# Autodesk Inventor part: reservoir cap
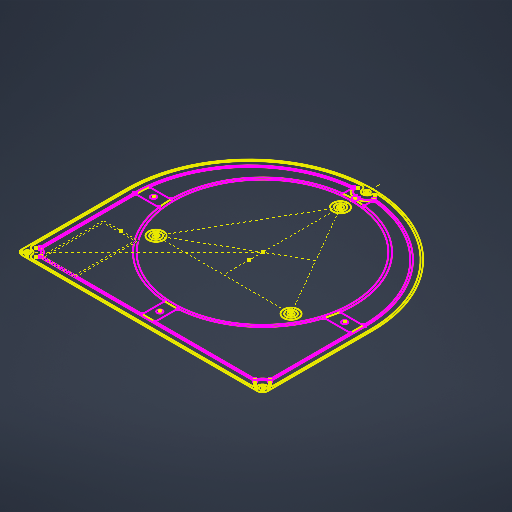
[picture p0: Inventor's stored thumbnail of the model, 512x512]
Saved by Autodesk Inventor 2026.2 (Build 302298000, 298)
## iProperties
Created: 2026-03
Part Number: reservoir cap
Material: Generic
Document SubType Name: Modeling
Designer: Tathagata Sikdar
Density: 1 g/cm^3
Appearance: Default
Author: Tathagata Sikdar
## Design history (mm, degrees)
derived "camera_base.ipt"
  sketch "Sketch1"
    geometry: L1 (0, -60.044)-(52, 30.022) reference; L2 (52, 30.022)-(-52, 30.022) reference; L3 (-52, 30.022)-(0, -60.044) reference; L4 (-26, -15.011)-(52, 30.022) reference; L5 (0, -60.044)-(0, 30.022) reference; L6 (94.574, 10.03)-(94.574, 90.574) reference; L7 (-94.574, 10.03)-(-94.574, 90.574) reference; L8 (90.574, 94.574)-(-90.574, 94.574) reference; L9 (93.154, 10.03)-(93.154, 84.168) reference; L10 (84.168, 93.154)-(-84.168, 93.154) reference; L11 (-93.154, 84.168)-(-93.154, 10.03) reference; L12 (88.994, 10.03)-(88.994, 82.391) reference; L13 (82.391, 88.994)-(-82.391, 88.994) reference; L14 (-88.994, 82.391)-(-88.994, 10.03) reference; L15 (-90.574, 90.574)-(-94.574, 94.574) reference; L16 (0, 0)-(90.574, 90.574) reference; L17 (82.089, 87.574)-(-82.089, 87.574) reference; L18 (-87.574, 82.089)-(-87.574, 10.03) reference; L19 (87.574, 10.03)-(87.574, 82.089) reference; L20 (80.971, 87.574)-(56.971, 87.574) reference; L21 (56.971, 87.574)-(56.971, 41.574) reference; L22 (56.971, 41.574)-(80.971, 41.574) reference; L23 (80.971, 41.574)-(80.971, 87.574) reference; L24 (82.391, 40.154)-(55.551, 40.154) reference; L25 (55.551, 40.154)-(55.551, 88.994) reference; L26 (55.551, 88.994)-(82.391, 88.994) reference; L27 (82.391, 88.994)-(82.391, 40.154) reference; C1 r 2 at (0, -60.044) reference; C2 r 2 at (-52, 30.022) reference; C3 r 2 at (52, 30.022) reference; C4 r 5.75 at (52, 30.022) reference; C5 r 3.75 at (52, 30.022) reference; C6 r 3.75 at (-52, 30.022) reference; C7 r 5.75 at (-52, 30.022) reference; C8 r 3.75 at (0, -60.044) reference; C9 r 5.75 at (0, -60.044) reference; C10 r 2 at (-90.574, 90.574) reference; C11 r 2 at (90.574, 90.574) reference; C12 r 2 at (0, -80.544) reference; C13 r 1 at (-92.696, 92.696) reference; A1 r 68.544 centre (0, 0) between (0, -68.544) and (55.551, 40.154) reference; A2 r 94.574 centre (0, 10.03) between (-94.574, 10.03) and (94.574, 10.03) reference; A3 r 3.42 centre (90.574, 90.574) between (87.162, 90.351) and (90.351, 87.162) reference; A4 r 3.42 centre (-90.574, 90.574) between (-90.351, 87.162) and (-87.162, 90.351) reference; A5 r 3.42 centre (0, -80.544) between (3.403, -80.2) and (-3.403, -80.2) reference; A6 r 3 centre (-90.154, 84.168) between (-90.351, 87.162) and (-93.154, 84.168) reference; A7 r 3 centre (-84.168, 90.154) between (-84.168, 93.154) and (-87.162, 90.351) reference; A8 r 3 centre (84.168, 90.154) between (87.162, 90.351) and (84.168, 93.154) reference; A9 r 3 centre (90.154, 84.168) between (93.154, 84.168) and (90.351, 87.162) reference; A10 r 93.154 centre (0, 10.03) between (6.6, -82.89) and (93.154, 10.03) reference; A11 r 93.154 centre (0, 10.03) between (-93.154, 10.03) and (-6.6, -82.89) reference; A12 r 7.58 centre (90.574, 90.574) between (83.345, 88.295) and (88.295, 83.345) reference; A13 r 7.58 centre (-90.574, 90.574) between (-88.295, 83.345) and (-83.345, 88.295) reference; A14 r 88.994 centre (0, 10.03) between (-88.994, 10.03) and (-8.149, -78.591) reference; A15 r 7.58 centre (0, -80.544) between (7.118, -77.939) and (-7.118, -77.939) reference; A16 r 88.994 centre (0, 10.03) between (8.149, -78.591) and (88.994, 10.03) reference; A17 r 1 centre (-87.994, 82.391) between (-88.295, 83.345) and (-88.994, 82.391) reference; A18 r 1 centre (-82.391, 87.994) between (-82.391, 88.994) and (-83.345, 88.295) reference; A19 r 1 centre (82.391, 87.994) between (83.345, 88.295) and (82.391, 88.994) reference; A20 r 1 centre (87.994, 82.391) between (88.994, 82.391) and (88.295, 83.345) reference; A21 r 1 centre (8.057, -77.595) between (7.118, -77.939) and (8.149, -78.591) reference; A22 r 1 centre (-8.057, -77.595) between (-8.149, -78.591) and (-7.118, -77.939) reference; A23 r 3 centre (-6.387, -79.898) between (-6.6, -82.89) and (-3.403, -80.2) reference; A24 r 3 centre (6.387, -79.898) between (3.403, -80.2) and (6.6, -82.89) reference; A25 r 4 centre (90.574, 90.574) between (94.574, 90.574) and (90.574, 94.574) reference; A26 r 4 centre (-90.574, 90.574) between (-90.574, 94.574) and (-94.574, 90.574) reference; A27 r 9 centre (90.574, 90.574) between (82.089, 87.574) and (87.574, 82.089) reference; A28 r 9 centre (-90.574, 90.574) between (-87.574, 82.089) and (-82.089, 87.574) reference; A29 r 87.574 centre (0, 10.03) between (-87.574, 10.03) and (-8.334, -77.147) reference; A30 r 9 centre (0, -80.544) between (8.334, -77.147) and (-8.334, -77.147) reference; A31 r 87.574 centre (0, 10.03) between (8.334, -77.147) and (87.574, 10.03) reference; 9 further points
    constraints: 1 other
sketch "Sketch3"
  geometry: L1 (88.994, 10.03)-(88.994, 82.391) reference; L2 (82.391, 88.994)-(-82.391, 88.994) reference; L3 (-88.994, 82.391)-(-88.994, 10.03) reference; L4 (87.002, 0.03)-(70.528, 0.03) reference; L5 (8.149, -76.723)-(8.149, -70.056) reference; L6 (-87.574, 20.03)-(-67.624, 20.03) reference; L7 (-87.574, 20.03)-(-87.574, 82.089) reference; L8 (-82.089, 87.574)-(-5, 87.574) reference; L9 (-5, 70.35)-(-5, 87.574) reference; L10 (-8.149, -76.723)-(-8.149, -70.056) reference; L11 (-69.811, 10.03)-(-87.574, 10.03) reference; L12 (5, 87.574)-(5, 70.35) reference; L13 (5, 87.574)-(82.089, 87.574) reference; L14 (87.574, 82.089)-(87.574, 10.03) reference; L15 (87.574, 10.03)-(69.811, 10.03) reference; C1 r 2 at (0, 79.051) reference; C2 r 2 at (-78.241, 15.03) reference; C3 r 2 at (78.89, 5.03) reference; C4 r 68.544 at (0, 0) reference; A1 r 2 centre (0, -71.544) between (1.288, -73.075) and (-1.288, -73.075) reference; A2 r 7.58 centre (0, -80.544) between (7.118, -77.939) and (1.288, -73.075) reference; A3 r 1 centre (8.057, -77.595) between (7.118, -77.939) and (8.149, -78.591) reference; A4 r 88.994 centre (0, 10.03) between (8.149, -78.591) and (88.994, 10.03) reference; A5 r 1 centre (87.994, 82.391) between (88.994, 82.391) and (88.295, 83.345) reference; A6 r 7.58 centre (90.574, 90.574) between (83.345, 88.295) and (88.295, 83.345) reference; A7 r 1 centre (82.391, 87.994) between (83.345, 88.295) and (82.391, 88.994) reference; A8 r 1 centre (-82.391, 87.994) between (-82.391, 88.994) and (-83.345, 88.295) reference; A9 r 7.58 centre (-90.574, 90.574) between (-88.295, 83.345) and (-83.345, 88.295) reference; A10 r 1 centre (-87.994, 82.391) between (-88.295, 83.345) and (-88.994, 82.391) reference; A11 r 88.994 centre (0, 10.03) between (-88.994, 10.03) and (-8.149, -78.591) reference; A12 r 1 centre (-8.057, -77.595) between (-8.149, -78.591) and (-7.118, -77.939) reference; A13 r 7.58 centre (0, -80.544) between (-1.288, -73.075) and (-7.118, -77.939) reference; A14 r 70.528 centre (0, 0) between (8.149, -70.056) and (70.528, 0.03) reference; A15 r 87.574 centre (0, 10.03) between (8.334, -77.147) and (87.002, 0.03) reference; A16 r 9 centre (0, -80.544) between (8.334, -77.147) and (8.149, -76.723) reference; A17 r 70.528 centre (0, 0) between (-5, 70.35) and (-67.624, 20.03) reference; A18 r 9 centre (-90.574, 90.574) between (-87.574, 82.089) and (-82.089, 87.574) reference; A19 r 9 centre (0, -80.544) between (-8.149, -76.723) and (-8.334, -77.147) reference; A20 r 87.574 centre (0, 10.03) between (-87.574, 10.03) and (-8.334, -77.147) reference; A21 r 70.528 centre (0, 0) between (-69.811, 10.03) and (-8.149, -70.056) reference; A22 r 9 centre (90.574, 90.574) between (82.089, 87.574) and (87.574, 82.089) reference; A23 r 70.528 centre (0, 0) between (69.811, 10.03) and (5, 70.35) reference; 1 further point
  node "Projected Loop1"
feature "Solid3::camera_base.ipt" dims "d0" = 10
tag "TaggingFeature1"
body "Solid3"
